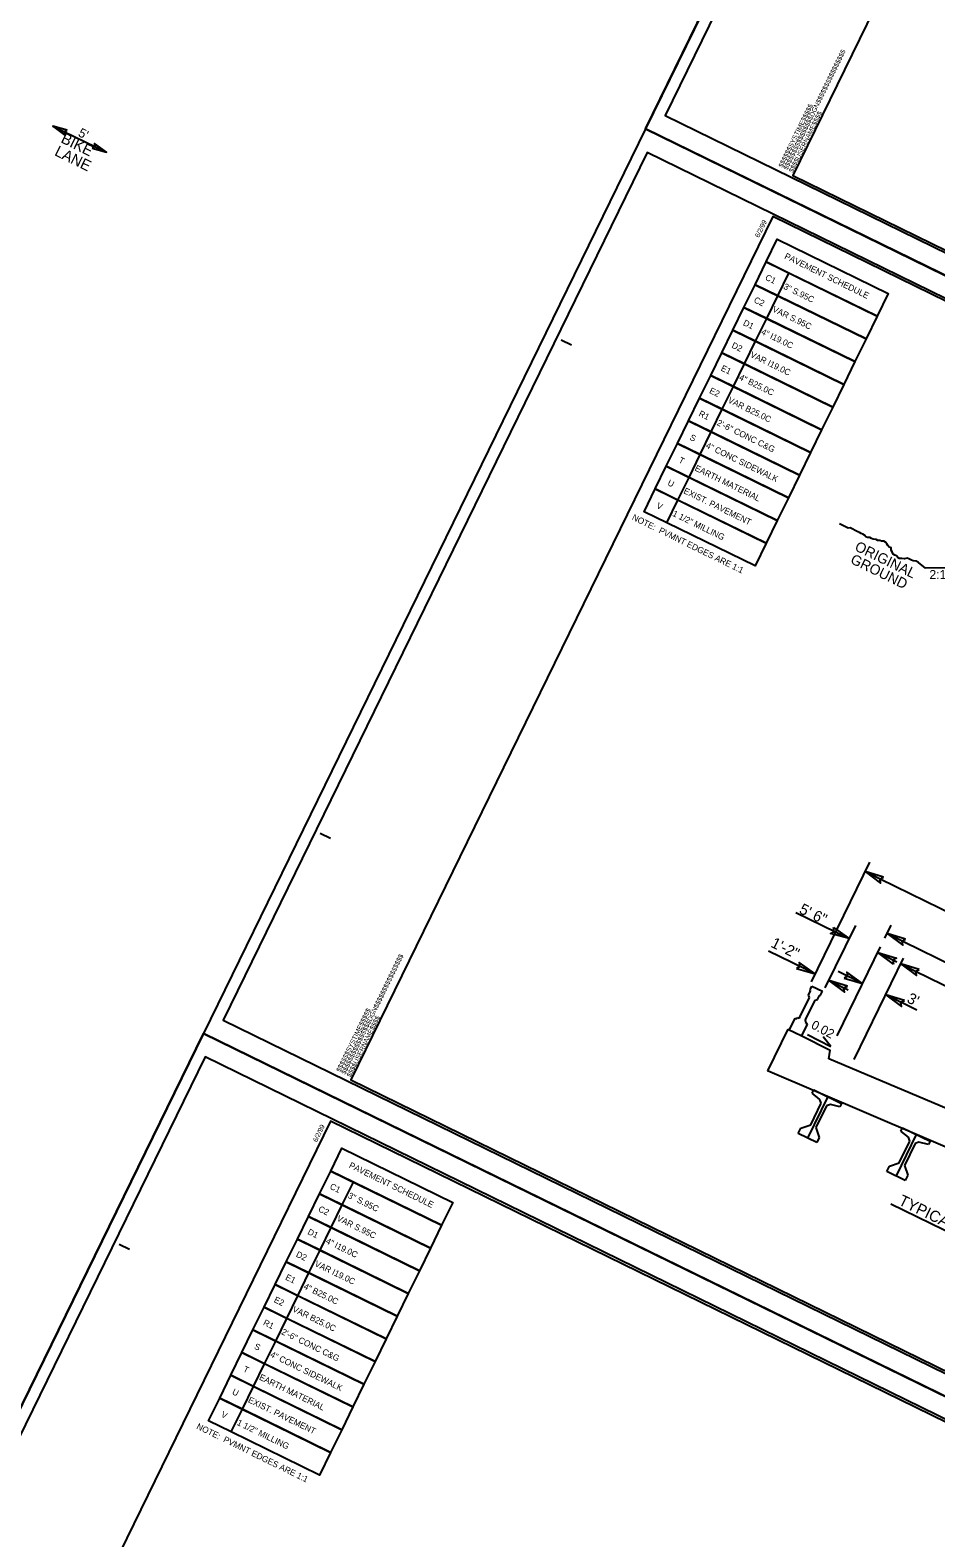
# Model space of a CAD drawing. Extents: x 1518247 to 1523638, y 635234 to 639927.
# Drawn here: x 1520253 to 1521243, y 637399 to 639046 of the extents above; entities that cross this region are included whole.
import ezdxf

# ---------------------------------------------------------------- set-up
doc = ezdxf.new("R2010")
doc.units = 0
for name, color, linetype in [('Default', 7, 'Continuous'), ('Default Symbol CELL', 7, 'Continuous'), ('Old_Level_1', 7, 'Continuous'), ('Old_Level_21', 7, 'Continuous'), ('Prop Conc Barrier', 7, 'Continuous'), ('Prop Dimension', 7, 'Continuous'), ('Prop Dimension Text', 7, 'Continuous'), ('Prop Pavement Schedule Description CELL', 7, 'Continuous'), ('Prop Shade Light', 7, 'Continuous'), ('Sheet Cutting Line CELL', 7, 'Continuous'), ('Sheet Plot Border Inside CELL', 7, 'Continuous'), ('Sheet Plot Border Outside CELL', 7, 'Continuous'), ('Sheet Typical CELL', 7, 'Continuous'), ('Typical Hinge Slope Arterial CELL', 7, 'Continuous'), ('Typical Hinge Slope Interstate CELL', 7, 'Continuous'), ('Typical Sidewalk and Rail CELL', 7, 'Continuous'), ('Typical Text Label CELL', 7, 'Continuous')]:
    doc.layers.add(name, color=color, linetype=linetype)

# ---------------------------------------------------------------- blocks, each defined once
blk = doc.blocks.new('TERMINATOR')
at = {"layer": 'Prop Shade Light'}
blk.add_lwpolyline([(-0.469, 0.081), (0, 0), (-0.471, -0.083), (-0.411, 0)], close=True, dxfattribs=at)

msp = doc.modelspace()

# ---------------------------------------------------------------- linework, layer by layer
at = {"layer": 'Default'}
for points in [[(1522438, 638198.6), (1520925.2, 638938.5), (1521408.5, 639926.6), (1522921.3, 639186.8)], [(1520442, 637950.3), (1521954.7, 637210.5), (1522438, 638198.6), (1520925.2, 638938.5)], [(1521471.5, 636222.3), (1519958.7, 636962.2), (1520442, 637950.3), (1521954.7, 637210.5)]]:
    msp.add_lwpolyline(points, close=True, dxfattribs=at)
at = {"layer": 'Default Symbol CELL'}
for p, q in [((1521124.5, 637881.2), (1521102.3, 637835.9)), ((1521107.6, 637885), (1521109.4, 637888.6)), ((1521115.9, 637878.2), (1521107.6, 637885)), ((1521109.4, 637888.6), (1521139.6, 637873.8)), ((1521117.4, 637874), (1521115.9, 637878.2)), ((1521105.8, 637850.2), (1521117.4, 637874)), ((1521123.1, 637871.2), (1521111.5, 637847.5)), ((1521127.4, 637872.6), (1521123.1, 637871.2)), ((1521137.8, 637870.2), (1521127.4, 637872.6)), ((1521139.6, 637873.8), (1521137.8, 637870.2)), ((1521092.3, 637840.8), (1521095.1, 637846.6)), ((1521095.1, 637846.6), (1521105.8, 637850.2)), ((1521111.5, 637847.4), (1521115.2, 637836.7)), ((1521204.4, 637843.6), (1521206.2, 637847.2)), ((1521212.7, 637836.9), (1521204.4, 637843.6)), ((1521206.2, 637847.2), (1521236.3, 637832.4)), ((1521112.4, 637831), (1521092.3, 637840.8)), ((1521115.2, 637836.7), (1521112.4, 637831)), ((1521221.2, 637839.8), (1521199.1, 637794.5)), ((1521202.6, 637808.9), (1521214.2, 637832.6)), ((1521219.9, 637829.8), (1521208.3, 637806.1)), ((1521214.2, 637832.6), (1521212.7, 637836.9)), ((1521224.2, 637831.3), (1521219.9, 637829.8)), ((1521234.6, 637828.8), (1521224.2, 637831.3)), ((1521236.3, 637832.4), (1521234.6, 637828.8)), ((1521189, 637799.5), (1521191.9, 637805.2)), ((1521209.2, 637789.6), (1521189, 637799.5)), ((1521191.9, 637805.2), (1521202.6, 637808.9)), ((1521208.3, 637806.1), (1521212, 637795.4)), ((1521212, 637795.4), (1521209.2, 637789.6))]:
    msp.add_line(p, q, dxfattribs=at)
at = {"layer": 'Old_Level_1'}
for p, q in [((1521102.3, 637948.9), (1521128, 637935.8)), ((1521128, 637935.8), (1521119.4, 637946.4)), ((1521586.4, 637683.7), (1521058.7, 637909.3)), ((1521555.2, 637741.1), (1521125.6, 637922.3))]:
    msp.add_line(p, q, dxfattribs=at)
for points in [[(1521185.5, 638121.1), (1521165.2, 638127.1), (1521182.3, 638114.5), (1521181.6, 638119)], [(1521130.7, 638066), (1521147.9, 638053.8), (1521127.4, 638059.5), (1521131.5, 638061.7)], [(1521209.6, 638053.3), (1521189.4, 638059.4), (1521206.5, 638046.7), (1521205.7, 638051.2)], [(1521090.2, 638021.2), (1521110.6, 638015.4), (1521093.3, 638027.8), (1521094.1, 638023.4)], [(1521196.2, 638026), (1521179.1, 638038.5), (1521199.6, 638032.5), (1521195.5, 638030.4)], [(1521224.5, 638020.1), (1521204.3, 638026.2), (1521221.4, 638013.6), (1521220.6, 638018.1)], [(1521145.9, 638002), (1521125.6, 638008.1), (1521142.7, 637995.4), (1521142, 637999.9)], [(1521142.3, 638010.6), (1521162.6, 638004.8), (1521145.4, 638017.2), (1521146.2, 638012.7)], [(1521208.2, 637986.3), (1521187.9, 637992.4), (1521205, 637979.7), (1521204.3, 637984.2)]]:
    msp.add_lwpolyline(points, close=True, dxfattribs=at)
at = {"layer": 'Prop Conc Barrier'}
for p, q in [((1521103.4, 637992.2), (1521105.6, 637996.7)), ((1521104.4, 637989.6), (1521103.4, 637992.2)), ((1521105.1, 637997.7), (1521107.2, 638002)), ((1521105.6, 637996.7), (1521105.1, 637997.7)), ((1521107.2, 638002), (1521118.7, 637996.3)), ((1521113.3, 637987.4), (1521115.5, 637991.8)), ((1521115.5, 637991.8), (1521116.6, 637992)), ((1521116.6, 637992), (1521118.7, 637996.3)), ((1521094.2, 637968.8), (1521104.4, 637989.6)), ((1521100.4, 637965.7), (1521110.6, 637986.5)), ((1521110.6, 637986.5), (1521113.3, 637987.4)), ((1521082.6, 637954.1), (1521088.9, 637966.9)), ((1521088.9, 637966.9), (1521090.7, 637966.1)), ((1521090.7, 637966.1), (1521091.5, 637967.8)), ((1521091.5, 637967.8), (1521093.3, 637967)), ((1521093.3, 637967), (1521094.2, 637968.8)), ((1521096, 637947.5), (1521102.3, 637960.4)), ((1521099.6, 637963.9), (1521100.4, 637965.7)), ((1521101.4, 637963), (1521099.6, 637963.9)), ((1521100.5, 637961.2), (1521101.4, 637963)), ((1521102.3, 637960.4), (1521100.5, 637961.2)), ((1521081, 637954.9), (1521096, 637947.5))]:
    msp.add_line(p, q, dxfattribs=at)
at = {"layer": 'Prop Dimension'}
for p, q in [((1520277.5, 638941.4), (1520335.9, 638912.9)), ((1521170.2, 638137.3), (1521106.3, 638006.6)), ((1521165.2, 638127.1), (1521679.1, 637875.8)), ((1521089.7, 638082.2), (1521147.9, 638053.8)), ((1521121.6, 637999.9), (1521155, 638068.2)), ((1521186.8, 638054.2), (1521193.8, 638068.5)), ((1521189.4, 638059.4), (1521611.7, 637852.8)), ((1521134.7, 637947.7), (1521182.2, 638044.8)), ((1521110.6, 638015.4), (1521059.8, 638040.2)), ((1521153.2, 637921.8), (1521207.4, 638032.6)), ((1521179.1, 638038.5), (1521200, 638028.3)), ((1521204.6, 638026), (1521576.2, 637844.3)), ((1521125.6, 638008.1), (1521146.9, 637997.7)), ((1521162.6, 638004.8), (1521135.9, 638017.8)), ((1521221.9, 637975.8), (1521187.9, 637992.4))]:
    msp.add_line(p, q, dxfattribs=at)
at = {"layer": 'Prop Pavement Schedule Description CELL'}
for points in [[(1521082, 638780.9), (1521057.2, 638793), (1521069.3, 638817.8), (1521190.6, 638758.5), (1521178.5, 638733.7), (1521082, 638780.9)], [(1521069.9, 638756.1), (1521045.1, 638768.2), (1521057.2, 638793), (1521178.5, 638733.7), (1521166.3, 638708.9), (1521069.9, 638756.1), (1521082, 638780.9)], [(1521057.7, 638731.3), (1521032.9, 638743.4), (1521045.1, 638768.2), (1521166.3, 638708.9), (1521154.2, 638684.1), (1521057.7, 638731.3), (1521069.9, 638756.1)], [(1521045.6, 638706.5), (1521020.8, 638718.6), (1521032.9, 638743.4), (1521154.2, 638684.1), (1521142.1, 638659.3), (1521045.6, 638706.5), (1521057.7, 638731.3)], [(1521033.5, 638681.7), (1521008.7, 638693.8), (1521020.8, 638718.6), (1521142.1, 638659.3), (1521130, 638634.5), (1521033.5, 638681.7), (1521045.6, 638706.5)], [(1521021.4, 638656.9), (1520996.5, 638669), (1521008.7, 638693.8), (1521130, 638634.5), (1521117.8, 638609.7), (1521021.4, 638656.9), (1521033.5, 638681.7)], [(1521009.2, 638632.1), (1520984.4, 638644.2), (1520996.5, 638669), (1521117.8, 638609.7), (1521105.7, 638584.9), (1521009.2, 638632.1), (1521021.4, 638656.9)], [(1520997.1, 638607.3), (1520972.3, 638619.4), (1520984.4, 638644.2), (1521105.7, 638584.9), (1521093.6, 638560.1), (1520997.1, 638607.3), (1521009.2, 638632.1)], [(1520985, 638582.5), (1520960.2, 638594.6), (1520972.3, 638619.4), (1521093.6, 638560.1), (1521081.4, 638535.3), (1520985, 638582.5), (1520997.1, 638607.3)], [(1520972.8, 638557.6), (1520948, 638569.8), (1520960.2, 638594.6), (1521081.4, 638535.3), (1521069.3, 638510.5), (1520972.8, 638557.6), (1520985, 638582.5)], [(1520960.7, 638532.8), (1520935.9, 638545), (1520948, 638569.8), (1521069.3, 638510.5), (1521057.2, 638485.7), (1520960.7, 638532.8), (1520972.8, 638557.6)], [(1520948.6, 638508), (1520923.8, 638520.2), (1520935.9, 638545), (1521057.2, 638485.7), (1521045, 638460.9), (1520948.6, 638508), (1520960.7, 638532.8)], [(1520606, 637787.8), (1520581.2, 637799.9), (1520593.3, 637824.7), (1520714.6, 637765.4), (1520702.4, 637740.6), (1520606, 637787.8)], [(1520593.8, 637763), (1520569, 637775.1), (1520581.2, 637799.9), (1520702.4, 637740.6), (1520690.3, 637715.8), (1520593.8, 637763), (1520606, 637787.8)], [(1520581.7, 637738.2), (1520556.9, 637750.3), (1520569, 637775.1), (1520690.3, 637715.8), (1520678.2, 637691), (1520581.7, 637738.2), (1520593.8, 637763)], [(1520569.6, 637713.4), (1520544.8, 637725.5), (1520556.9, 637750.3), (1520678.2, 637691), (1520666, 637666.2), (1520569.6, 637713.4), (1520581.7, 637738.2)], [(1520557.4, 637688.6), (1520532.6, 637700.7), (1520544.8, 637725.5), (1520666, 637666.2), (1520653.9, 637641.4), (1520557.4, 637688.6), (1520569.6, 637713.4)], [(1520545.3, 637663.7), (1520520.5, 637675.9), (1520532.6, 637700.7), (1520653.9, 637641.4), (1520641.8, 637616.6), (1520545.3, 637663.7), (1520557.4, 637688.6)], [(1520533.2, 637638.9), (1520508.4, 637651.1), (1520520.5, 637675.9), (1520641.8, 637616.6), (1520629.6, 637591.8), (1520533.2, 637638.9), (1520545.3, 637663.7)], [(1520521, 637614.1), (1520496.2, 637626.3), (1520508.4, 637651.1), (1520629.6, 637591.8), (1520617.5, 637567), (1520521, 637614.1), (1520533.2, 637638.9)], [(1520508.9, 637589.3), (1520484.1, 637601.5), (1520496.2, 637626.3), (1520617.5, 637567), (1520605.4, 637542.2), (1520508.9, 637589.3), (1520521, 637614.1)], [(1520496.8, 637564.5), (1520472, 637576.7), (1520484.1, 637601.5), (1520605.4, 637542.2), (1520593.2, 637517.3), (1520496.8, 637564.5), (1520508.9, 637589.3)], [(1520484.6, 637539.7), (1520459.8, 637551.9), (1520472, 637576.7), (1520593.2, 637517.3), (1520581.1, 637492.5), (1520484.6, 637539.7), (1520496.8, 637564.5)], [(1520472.5, 637514.9), (1520447.7, 637527), (1520459.8, 637551.9), (1520581.1, 637492.5), (1520569, 637467.7), (1520472.5, 637514.9), (1520484.6, 637539.7)]]:
    msp.add_lwpolyline(points, dxfattribs=at)
at = {"layer": 'Sheet Cutting Line CELL'}
for p, q in [((1521408.5, 639926.6), (1520925.2, 638938.5)), ((1520925.2, 638938.5), (1520442, 637950.3)), ((1520925.2, 638938.5), (1522438, 638198.6)), ((1522438, 638198.6), (1520925.2, 638938.5)), ((1520442, 637950.3), (1519958.7, 636962.2)), ((1520442, 637950.3), (1521954.7, 637210.5)), ((1521954.7, 637210.5), (1520442, 637950.3))]:
    msp.add_line(p, q, dxfattribs=at)
at = {"layer": 'Sheet Plot Border Inside CELL'}
for points in [[(1522907.4, 639168.6), (1521410.3, 639900.8), (1520946.8, 638952.9), (1522443.8, 638220.8)], [(1522424.1, 638180.4), (1520927.1, 638912.6), (1520463.5, 637964.8), (1521960.6, 637232.6)], [(1521940.8, 637192.3), (1520443.8, 637924.5), (1519980.2, 636976.6), (1521477.3, 636244.5)]]:
    msp.add_lwpolyline(points, close=True, dxfattribs=at)
at = {"layer": 'Sheet Plot Border Outside CELL'}
for points in [[(1522921.3, 639186.8), (1521408.5, 639926.6), (1520925.2, 638938.5), (1522438, 638198.6)], [(1522438, 638198.6), (1520925.2, 638938.5), (1520442, 637950.3), (1521954.7, 637210.5)], [(1521954.7, 637210.5), (1520442, 637950.3), (1519958.7, 636962.2), (1521471.5, 636222.3)]]:
    msp.add_lwpolyline(points, close=True, dxfattribs=at)
at = {"layer": 'Sheet Typical CELL'}
for p, q in [((1521086.3, 638887.6), (1521086.3, 638887.6)), ((1521086.3, 638887.6), (1521086.3, 638887.6)), ((1521086.3, 638887.6), (1521086.3, 638887.6)), ((1521086.3, 638887.6), (1521086.3, 638887.6)), ((1521086.3, 638887.6), (1521086.3, 638887.6)), ((1521086.3, 638887.6), (1521086.3, 638887.6)), ((1520833.1, 638708), (1520844.4, 638702.5)), ((1520569.5, 638169), (1520580.8, 638163.5)), ((1520603, 637899.4), (1520603, 637899.4)), ((1520603, 637899.4), (1520603, 637899.4)), ((1520603, 637899.4), (1520603, 637899.4)), ((1520603, 637899.4), (1520603, 637899.4)), ((1520603, 637899.4), (1520603, 637899.4)), ((1520603, 637899.4), (1520603, 637899.4)), ((1520349.8, 637719.9), (1520361.1, 637714.4))]:
    msp.add_line(p, q, dxfattribs=at)
for points in [[(1522895, 639171.8), (1521547.6, 639830.8), (1521086.3, 638887.6), (1522433.7, 638228.6)], [(1522411.8, 638183.6), (1521064.3, 638842.7), (1520603, 637899.4), (1521950.4, 637240.4)], [(1521928.5, 637195.5), (1520581, 637854.5), (1520119.7, 636911.3), (1521467.2, 636252.3)]]:
    msp.add_lwpolyline(points, close=True, dxfattribs=at)
for points in [[(1521119.9, 638871.1), (1521119.9, 638871.1)], [(1520636.7, 637883), (1520636.7, 637883)]]:
    msp.add_lwpolyline(points, dxfattribs=at)
at = {"layer": 'Typical Hinge Slope Interstate CELL'}
msp.add_line((1521307.7, 638459.2), (1521231.4, 638458.4), dxfattribs=at)
msp.add_lwpolyline([(1521231.4, 638458.4), (1521223.8, 638464.7), (1521221, 638466), (1521217.8, 638466.5), (1521215.9, 638467.4), (1521213.1, 638468.7), (1521211.3, 638469.6), (1521208.5, 638468.7), (1521205.3, 638469.1), (1521202.9, 638469.1), (1521201.1, 638470), (1521199.7, 638471.8), (1521197.8, 638472.7), (1521196, 638473.7), (1521195, 638476.4), (1521193.6, 638478.3), (1521193.6, 638480.6), (1521191.7, 638481.5), (1521190.3, 638483.3), (1521188.9, 638485.2), (1521187.5, 638487), (1521185.7, 638487.9), (1521183.3, 638487.9), (1521181.5, 638488.8), (1521179.2, 638488.8), (1521177.3, 638489.7), (1521174.1, 638490.1), (1521172.2, 638491), (1521170.3, 638491.9), (1521168, 638491.9), (1521166.2, 638492.8), (1521164.8, 638494.6), (1521162.9, 638495.5), (1521161.1, 638496.5), (1521159.2, 638497.4), (1521157.3, 638498.3), (1521154.5, 638499.6), (1521151.8, 638501), (1521149, 638502.4), (1521146.7, 638502.3), (1521143.9, 638503.7), (1521141.1, 638505.1), (1521137.4, 638506.9)], dxfattribs=at)
at = {"layer": 'Typical Sidewalk and Rail CELL'}
for p, q in [((1521081, 637954.9), (1521058.7, 637909.3)), ((1521096, 637947.5), (1521127.1, 637932)), ((1521125.6, 637922.3), (1521127.1, 637932))]:
    msp.add_line(p, q, dxfattribs=at)
at = {"layer": 'Typical Text Label CELL'}
msp.add_line((1521193.4, 637764.2), (1521375.3, 637675), dxfattribs=at)

# ---------------------------------------------------------------- block references
at = {"layer": 'Prop Dimension', "xscale": 33.82820784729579, "yscale": -36.41552511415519}
for p, rotation in [((1520277.5, 638941.4), 153.97926941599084), ((1520335.9, 638912.9), -26.020730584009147)]:
    msp.add_blockref('TERMINATOR', p, dxfattribs=dict(at, rotation=rotation))

# ---------------------------------------------------------------- texts
at = {"layer": 'Old_Level_1'}
msp.add_text('0.02', height=9.97, rotation=331.9538, dxfattribs=at).set_placement((1521105.4, 637956.4))
at = {"layer": 'Old_Level_21'}
for p in [(1520909.8, 638511.8), (1520433.8, 637518.7)]:
    msp.add_text('NOTE:  PVMNT EDGES ARE 1:1', height=6.75, rotation=333.8298, dxfattribs=at).set_placement(p)
at = {"layer": 'Prop Dimension'}
for s, height, rotation, p in [('BIKE', 11.87, 333.7408, (1520285.3, 638924)), ("5'", 9.97, 333.9793, (1520304.3, 638930.9)), ('LANE', 11.87, 333.7408, (1520278.4, 638910)), ('5\' 6"', 11.87, 334.1346, (1521092.3, 638082.1)), ('1\'-2"', 11.87, 333.7408, (1521061.4, 638045.2)), ("3'", 11.87, 333.7408, (1521210, 637984.7))]:
    msp.add_text(s, height=height, rotation=rotation, dxfattribs=at).set_placement(p)
at = {"layer": 'Prop Dimension Text'}
msp.add_text('TYPICAL SECTION NO. 3', height=12.23, rotation=334.0511, dxfattribs=at).set_placement((1521200.8, 637763.6))
at = {"layer": 'Prop Pavement Schedule Description CELL'}
for s, p in [('PAVEMENT SCHEDULE', (1521076.5, 638797.1)), ('C1', (1521055.5, 638773.9)), ('3" S.95C', (1521075.4, 638764)), ('C2', (1521043, 638749.3)), ('VAR S.95C', (1521063.3, 638739.2)), ('D1', (1521031.3, 638724.3)), ('4" I19.0C', (1521051.1, 638714.4)), ('D2', (1521018.7, 638699.7)), ('VAR I19.0C', (1521039, 638689.5)), ('E1', (1521007, 638674.7)), ('4" B25.0C', (1521026.9, 638664.7)), ('E2', (1520994.4, 638650.1)), ('VAR B25.0C', (1521014.7, 638639.9)), ('R1', (1520982.7, 638625.1)), ('2\'-6" CONC C&G', (1521002.6, 638615.1)), ('S', (1520973, 638599.1)), ('4" CONC SIDEWALK', (1520990.5, 638590.3)), ('T', (1520960.8, 638574.3)), ('EARTH MATERIAL', (1520978.4, 638565.5)), ('U', (1520948.7, 638549.5)), ('EXIST. PAVEMENT', (1520966.2, 638540.7)), ('V', (1520936.6, 638524.7)), ('1 1/2" MILLING', (1520954.1, 638515.9)), ('PAVEMENT SCHEDULE', (1520600.5, 637803.9)), ('C1', (1520579.5, 637780.8)), ('C2', (1520566.9, 637756.2)), ('3" S.95C', (1520599.4, 637770.8)), ('VAR S.95C', (1520587.2, 637746)), ('D1', (1520555.2, 637731.2)), ('D2', (1520542.6, 637706.6)), ('4" I19.0C', (1520575.1, 637721.2)), ('VAR I19.0C', (1520563, 637696.4)), ('E1', (1520530.9, 637681.6)), ('E2', (1520518.4, 637657)), ('4" B25.0C', (1520550.8, 637671.6)), ('VAR B25.0C', (1520538.7, 637646.8)), ('R1', (1520506.7, 637632)), ('2\'-6" CONC C&G', (1520526.6, 637622)), ('S', (1520496.9, 637606)), ('4" CONC SIDEWALK', (1520514.4, 637597.2)), ('T', (1520484.8, 637581.2)), ('EARTH MATERIAL', (1520502.3, 637572.4)), ('U', (1520472.7, 637556.4)), ('EXIST. PAVEMENT', (1520490.2, 637547.6)), ('V', (1520460.6, 637531.6)), ('1 1/2" MILLING', (1520478, 637522.8))]:
    msp.add_text(s, height=6.75, rotation=333.9377, dxfattribs=at).set_placement(p)
at = {"layer": 'Sheet Typical CELL'}
for s, p in [('$$$$$$$$$$$$$$$$DGN$$$$$$$$$$$$$$$$', (1521080.4, 638893.1)), ('$$$$$$SYSTIME$$$$$', (1521075, 638895.7)), ('$$$$USERNAME$$$$', (1521086.3, 638890.2)), ('6/2/99', (1521049.3, 638819.1)), ('$$$$$$$$$$$$$$$$DGN$$$$$$$$$$$$$$$$', (1520597.1, 637904.9)), ('$$$$$$SYSTIME$$$$$', (1520591.7, 637907.6)), ('$$$$USERNAME$$$$', (1520603, 637902)), ('6/2/99', (1520566, 637831))]:
    msp.add_text(s, height=5.25, rotation=63.9377, dxfattribs=at).set_placement(p)
at = {"layer": 'Typical Hinge Slope Arterial CELL'}
msp.add_text('2:1 TO 6:1', height=9.97, rotation=0.2071, dxfattribs=at).set_placement((1521235.6, 638446.5))
at = {"layer": 'Typical Hinge Slope Interstate CELL'}
for s, p in [('ORIGINAL', (1521153.1, 638478.4)), ('GROUND', (1521148.3, 638464.4))]:
    msp.add_text(s, height=11.21, rotation=334.0511, dxfattribs=at).set_placement(p)

doc.saveas('drawing.dxf')
